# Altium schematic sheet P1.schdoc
size 210 x 148 mm; Page Size: A5; Title Block: 1; Symbol: Drawing-Symbol_A4; Drawed: ResAlexander; Reviewed: ResAlexander; Version: V1.0; @Project Name: 正在加载中...挂件; @Update Date: 2026-03-13; @Create Date: 2026-03-13; Device: Drawing-Symbol_A4; @Board Name: Board2; @Page Name: P1; @Create Time: 05:53:25; @Page Count: 1; @Page No: 1; @Schematic Name: Schematic2; @Update Time: 05:53:25; @Assembly Variant: Basic; Border: 1; Title Block Position: 3; Size: A4; Width: 826; Height: 582; Region Start: 1; X Region Count: 6; Y Region Count: 4; Blade Width: 10
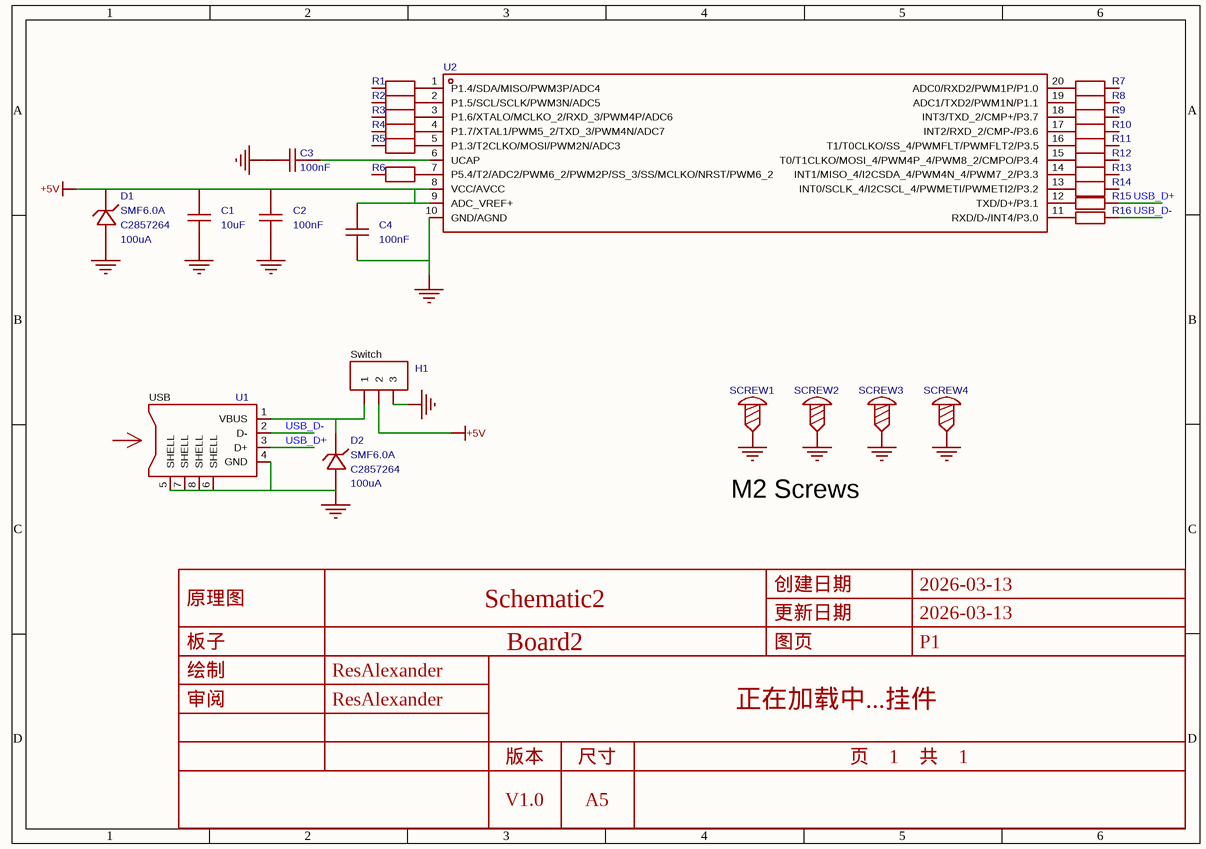
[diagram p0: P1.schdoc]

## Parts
C1  10uF  [C1206]
C2  100nF  [C0603]
C3  100nF  [C0603]
C4  100nF  [C0603]
D1  Supplier Part: C2857264  Reverse Leakage Current (Ir): 100uA  [SOD-123FL_L2.8-W1.9-LS3.7-RD]  (hidden comment: SMF6.0A)
D2  Supplier Part: C2857264  Reverse Leakage Current (Ir): 100uA  [SOD-123FL_L2.8-W1.9-LS3.7-RD]  (hidden comment: SMF6.0A)
H1  2.54-1*3P针  [HDR-TH_3P-P2.54-V-M-1]  (value not drawn)
R1  220Ω  [R0603]  (value not drawn)
R2  220Ω  [R0603]  (value not drawn)
R3  220Ω  [R0603]  (value not drawn)
R4  220Ω  [R0603]  (value not drawn)
R5  220Ω  [R0603]  (value not drawn)
R6  220Ω  [R0603]  (value not drawn)
R7  220Ω  [R0603]  (value not drawn)
R8  220Ω  [R0603]  (value not drawn)
R9  220Ω  [R0603]  (value not drawn)
R10  220Ω  [R0603]  (value not drawn)
R11  220Ω  [R0603]  (value not drawn)
R12  220Ω  [R0603]  (value not drawn)
R13  220Ω  [R0603]  (value not drawn)
R14  220Ω  [R0603]  (value not drawn)
R15  22Ω  [R0603]  (value not drawn)
R16  22Ω  [R0603]  (value not drawn)
SCREW1  (no value)  [M2螺丝]
SCREW2  (no value)  [M2螺丝]
SCREW3  (no value)  [M2螺丝]
SCREW4  (no value)  [M2螺丝]
U1  XUBF-012-0404  [USB-A-TH_XUBF-012-0404]  (value not drawn)
U2  STC8H8K64U-45I-TSSOP20  [TSSOP-20_L6.5-W4.4-P0.65-LS6.5-BL]  (value not drawn)

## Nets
+5V: C1.2 C2.2 C4.2 D1.1(C) H1.2 U2.8(VCC/AVCC) U2.9(ADC_VREF+)
GND: C1.1 C2.1 C3.2 C4.1 D1.2(A) D2.2(A) H1.3 SCREW1.1 SCREW2.1 SCREW3.1 SCREW4.1 U1.4(GND) U1.5(SHELL) U1.6(SHELL) U1.7(SHELL) U1.8(SHELL) U2.10(GND/AGND)
USB_D+: R15.2 U1.3(D+)
USB_D-: R16.2 U1.2(D-)
NetC3_1: C3.1 U2.6(UCAP)
NetD2_1: D2.1(C) H1.1 U1.1(VBUS)
NetR1_2: R1.2 U2.1(P1.4/SDA/MISO/PWM3P/ADC4)
NetR2_2: R2.2 U2.2(P1.5/SCL/SCLK/PWM3N/ADC5)
NetR3_2: R3.2 U2.3(P1.6/XTALO/MCLKO_2/RXD_3/PWM4P/ADC6)
NetR4_2: R4.2 U2.4(P1.7/XTAL1/PWM5_2/TXD_3/PWM4N/ADC7)
NetR5_2: R5.2 U2.5(P1.3/T2CLKO/MOSI/PWM2N/ADC3)
NetR6_2: R6.2 U2.7(P5.4/T2/ADC2/PWM6_2/PWM2P/SS_3/SS/MCLKO/NRST/PWM6_2)
NetR7_1: R7.1 U2.20(ADC0/RXD2/PWM1P/P1.0)
NetR8_1: R8.1 U2.19(ADC1/TXD2/PWM1N/P1.1)
NetR9_1: R9.1 U2.18(INT3/TXD_2/CMP+/P3.7)
NetR10_1: R10.1 U2.17(INT2/RXD_2/CMP-/P3.6)
NetR11_1: R11.1 U2.16(T1/T0CLKO/SS_4/PWMFLT/PWMFLT2/P3.5)
NetR12_1: R12.1 U2.15(T0/T1CLKO/MOSI_4/PWM4P_4/PWM8_2/CMPO/P3.4)
NetR13_1: R13.1 U2.14(INT1/MISO_4/I2CSDA_4/PWM4N_4/PWM7_2/P3.3)
NetR14_1: R14.1 U2.13(INT0/SCLK_4/I2CSCL_4/PWMETI/PWMETI2/P3.2)
NetR15_1: R15.1 U2.12(TXD/D+/P3.1)
NetR16_1: R16.1 U2.11(RXD/D-/INT4/P3.0)

Not connected (* = marked no-connect by the designer): R1 1; R2 1; R3 1; R4 1; R5 1; R6 1; R7 2; R8 2; R9 2; R10 2; R11 2; R12 2; R13 2; R14 2

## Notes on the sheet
- (near H1) Switch
- (near U1) USB
- M2 Screws

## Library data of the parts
C1 = CL31B106KAHNNNE: 容值:10uF;精度:±10%;额定电压:25V;温度系数:X7R;; Manufacturer: SAMSUNG(三星); AddInBom: yes; ModelId: e4be705b945545a48e666415e3682bd80819f05c4eef4c71ace90d822a990e87; ModelName: C1206_L3.2-W1.6-H1.3; ModelTransform: 125.984,62.992,0,0,0,0,0,0,0; Tolerance: ±10%; Voltage Rating: 25V; Temperature Coefficient: X7R
C2 C4 = FCC0603B104K500CT: 容值:100nF;精度:±10%;额定电压:50V;温度系数:X7R;; Manufacturer: FOJAN(富捷); AddInBom: yes; ModelId: ac125912035d415993ca9572d50418b10819f05c4eef4c71ace90d822a990e87; ModelName: C0603_L1.6-W0.8-H0.8; ModelTransform: 62.992,31.496,0,0,0,0,0,0,0; Tolerance: ±10%; Voltage Rating: 50V; Temperature Coefficient: X7R
C3 = FCC0603B104K500CT: 容值:100nF;精度:±10%;额定电压:50V;温度系数:X7R;; Manufacturer: FOJAN(富捷); 3D Model: ac125912035d415993ca9572d50418b10819f05c4eef4c71ace90d822a990e87; 3D Model Transform: 62.992,31.496,0,0,0,0,0,0,0; Tolerance: ±10%; Voltage Rating: 50V; Temperature Coefficient: X7R; AddInBom: yes; ModelName: C0603_L1.6-W0.8-H0.8
D1 D2 = SMF6.0A_C2857264: 反向截止电压(Vrwm):6V;钳位电压:10.3V;峰值脉冲电流(Ipp):19.4A;峰值脉冲功率(Ppp):200W;击穿电压:6.7V;; Manufacturer: JSMSEMI(杰盛微); Clamping Voltage: 10.3V; Reverse Stand-Off Voltage (Vrwm): 6V; 3D Model: ee80cc4b5e2f4a0b8a944bbfc66c96ba0819f05c4eef4c71ace90d822a990e87; 3D Model Transform: 141.732,74.803,0,0,0,0,0,0,0; Peak Pulse Current (Ipp): 19.4A; Peak Pulse Power Dissipation (Ppp): 200W; Voltage - Breakdown: 6.7V; Type: TVS; AddInBom: yes
H1 = 2.54-1*3P针: 插针结构:1x3P;间距:2.54mm;行距:-;圆针/方针:方针;安装方式:直插;排数:单排;总PIN位数:3P;额定电流:3A;额定电压:-;配合针长度:6mm;塑高:2.5mm;端接针长度:3mm;触头材质:黄铜;触头镀层:金;工作温度:-40℃~+105℃;颜色:黑色;; Manufacturer: BOOMELE(博穆精密); Symbol: Header-Male-2.54_1x3; AddInBom: yes; ModelId: 94a8ffe137b6410295cb18cd3ffd99db0819f05c4eef4c71ace90d822a990e87; ModelName: HDR-M-2.54_1x3; ModelTransform: 299.9994,100,0,0,0,0,0,0,-118.11; Pin Structure: 1x3P; Pitch: 2.54mm; Circluar Pins/Square Pins: 方针; Current Rating: 3A
R1-R14 = RCA03220RJLF: 电阻类型:厚膜电阻;阻值:220Ω;精度:±5%;功率:100mW;工作电压:75V;温度系数:±100ppm/℃;; Manufacturer: HKR(香港电阻); AddInBom: yes; ModelId: fc143cca1e79419f9cd78b61e9279f080819f05c4eef4c71ace90d822a990e87; ModelTransform: 31.8897,63.7794,0,90,0,0,0,0,0; Tolerance: ±5%; Power(Watts): 100mW; Voltage-Supply(Max): 75V
R15 R16 = 0603WAF220JT5E: 电阻类型:厚膜电阻;阻值:22Ω;精度:±1%;功率:100mW;最大工作电压:75V;温度系数:±100ppm/℃;; Manufacturer: UNI-ROYAL(厚声); AddInBom: yes; ModelId: fc143cca1e79419f9cd78b61e9279f080819f05c4eef4c71ace90d822a990e87; ModelTransform: 31.8897,63.7794,0,90,0,0,0,0,0; Tolerance: ±1%; Power(Watts): 100mW; Overload Voltage (Max): 75V
SCREW1-SCREW4 = M2螺丝: Symbol: 螺丝孔; ConvertToPcb: yes
U1 = XUBF-012-0404: 连接器类型:Type-A;协议标准:USB 2.0;公母:母;安装方式:弯插;触点数量:4P;端口数量:1;额定电流 - 电源:3A;工作温度:-40℃~+85℃;; Manufacturer: LX(连欣科技); Protocol Standard: USB 2.0; Gender: 母; 3D Model: 7b788225ce8b462db7642ff341303647; 3D Model Transform: 574.802,393.7,0,0,0,0,0,-43.189,-90.551; Connector Type: Type-A; Number of Contacts: 4P; Number of Ports: 1; Current Rating-Power: 3A; AddInBom: yes
U2 = STC8H8K64U-45I-TSSOP20: Manufacturer: STC; AddInBom: yes; ModelId: b95f5f32e2b245dbbeaae7dbe3e931630819f05c4eef4c71ace90d822a990e87; ModelTransform: 255.905,251.968,0,0,0,0,0,0,0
